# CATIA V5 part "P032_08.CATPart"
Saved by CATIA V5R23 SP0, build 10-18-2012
Part number: P032_08
Bounding box of the stored display mesh (mm): x 19.163 to 19.613, y -14.784 to 14.784, z -14.784 to 14.784
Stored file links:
  C:\wamp\www\COURS\CONCEPTION GMP1\TITRE 02-SEMESTRE 2\03-TP7-PRESSE MECANIQUE\eleve\P032_08.CATPart
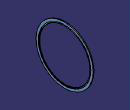
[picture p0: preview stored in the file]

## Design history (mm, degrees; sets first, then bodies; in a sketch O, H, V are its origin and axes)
Body1 (main body)
  Solid1: solid without history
